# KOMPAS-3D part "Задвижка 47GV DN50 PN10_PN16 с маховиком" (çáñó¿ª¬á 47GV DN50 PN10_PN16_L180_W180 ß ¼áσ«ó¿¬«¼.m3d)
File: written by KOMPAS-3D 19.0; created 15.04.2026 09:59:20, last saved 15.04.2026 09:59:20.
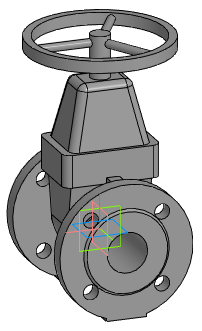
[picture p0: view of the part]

Document properties: Автор: Евгений; Полное имя файла: Z:\3.Личные\kachalov\3d для проектировщиков\2.1 Тип 47GV, 47GV.Z\Задвижка 47GV_DN40-DN600\stp_Задвижка 47GV\Задвижка 47GV DN50 PN10_PN16_L180_W180 с маховиком.m3d

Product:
- Part/product: Задвижка 47GV DN50 PN10_PN16 с маховиком

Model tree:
1. Операция без истории:1  (labels: Задвижка 47GV DN50 PN10_PN16 с маховиком)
